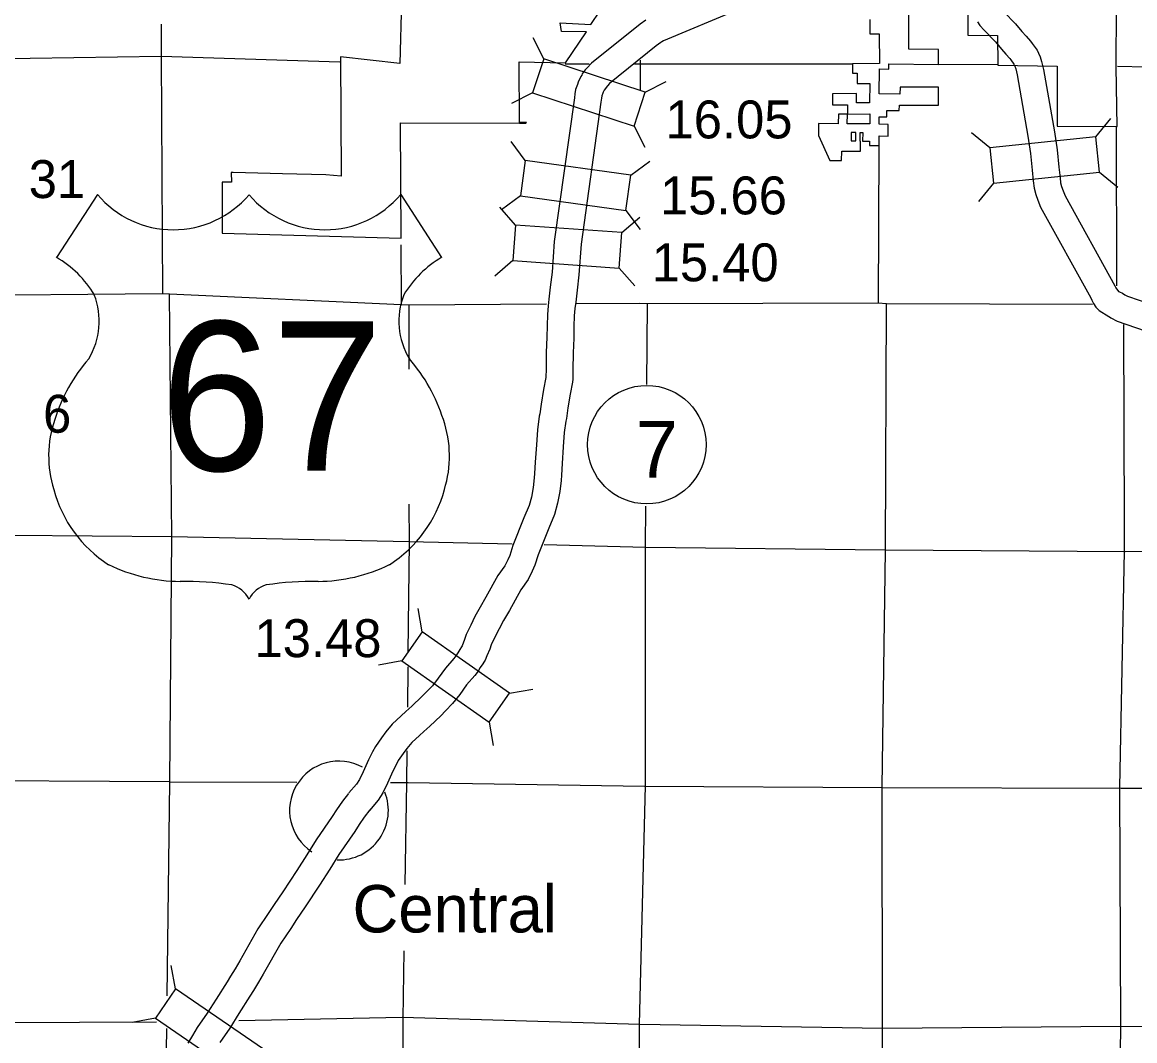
# Model space of a CAD drawing. Extents: x 369523 to 838377, y 495025 to 936819.
# Drawn here: x 641756 to 666534, y 838052 to 860745 of the extents above; entities that cross this region are included whole.
import ezdxf

# ---------------------------------------------------------------- set-up
doc = ezdxf.new("R2010")
doc.units = 0
for name, color, linetype in [('1', 7, 'Continuous'), ('6', 7, 'Continuous'), ('DSN_DRFT_Common-Line', 7, 'Continuous'), ('DSN_DRFT_Junk-No-Plot', 7, 'Continuous'), ('Level 1', 7, 'Continuous'), ('Level 11', 7, 'Continuous'), ('Level 15', 7, 'Continuous'), ('Level 2', 7, 'Continuous'), ('Level 21', 7, 'Continuous'), ('Level 22', 7, 'Continuous')]:
    doc.layers.add(name, color=color, linetype=linetype)

msp = doc.modelspace()

# ---------------------------------------------------------------- linework, layer by layer
at = {"layer": '1'}
for start, end in [(61.3406, 236.6749), (268.0667, 21.9061)]:
    msp.add_arc((648810, 843182), 1100, start, end, dxfattribs=at)
at = {"layer": '6'}
for p, q in [((643430, 856908), (642521, 855503)), ((650186, 856908), (651095, 855503))]:
    msp.add_line(p, q, dxfattribs=at)
for centre, radius, start, end in [((645122, 858332), 2211, 220.075, 319.6701), ((648494, 858332), 2211, 220.3299, 319.925), ((641334, 853463), 2361, 30.7809, 59.9883), ((652282, 853463), 2361, 120.0117, 149.2191), ((641853, 854085), 1618, 328.8105, 21.2108), ((651762, 854085), 1618, 158.7892, 211.1895), ((646085, 850768), 3776, 138.9565, 162.6913), ((647530, 850768), 3776, 17.3087, 41.0435), ((644839, 851077), 2495, 160.9576, 197.3819), ((648777, 851077), 2495, 342.6181, 19.0424), ((645245, 851084), 2887, 195.1074, 237.1312), ((648371, 851084), 2887, 302.8688, 344.8926), ((645299, 851994), 3707, 244.0771, 269.5779), ((648317, 851994), 3707, 270.4221, 295.9229), ((645384, 841498), 6790, 81.1942, 90.9539), ((646234, 847586), 651, 28.0342, 72.9864), ((647382, 847586), 651, 107.0136, 151.9658), ((648231, 841498), 6790, 89.0461, 98.8058)]:
    msp.add_arc(centre, radius, start, end, dxfattribs=at)
at = {"layer": 'DSN_DRFT_Common-Line'}
msp.add_circle((655666, 851334), 1320, dxfattribs=at)
at = {"layer": 'Level 1'}
for points in [[(663621, 860979), (663876, 860708), (664022, 860538), (664115, 860433), (664212, 860322), (664253, 860270), (664360, 860123), (664394, 860054), (664425, 859972), (664460, 859873), (664500, 859694), (664744, 858305), (664807, 857899), (664846, 857513), (664870, 857278), (664884, 857165), (664905, 857089), (664940, 856989), (664981, 856881), (666089, 854873), (666112, 854824), (666112, 854824), (666174, 854749), (666180, 854745), (666193, 854738), (666260, 854712), (666313, 854673), (666375, 854642), (667673, 854193)], [(663029, 860755), (663086, 860672), (663184, 860568), (663430, 860306), (663569, 860144), (663664, 860036), (663751, 859938), (663775, 859907), (663844, 859813), (663862, 859765), (663882, 859708), (663912, 859576), (664152, 858208), (664211, 857823), (664249, 857453), (664274, 857212), (664293, 857049), (664332, 856909), (664377, 856782), (664436, 856628), (665554, 854603), (665577, 854552), (665616, 854481), (665669, 854395), (665742, 854319), (665956, 854186), (665969, 854181), (666001, 854158), (666144, 854087), (667393, 853655)]]:
    msp.add_lwpolyline(points, dxfattribs=at)
at = {"layer": 'Level 11'}
for points in [[(655644, 860791), (655518, 860705), (654438, 859830), (654339, 859732), (654296, 859684), (654229, 859593), (654216, 859565), (654194, 859534), (654139, 859412), (654120, 859360), (654081, 859243), (654067, 859147), (654053, 859060), (653604, 855862), (653556, 855177), (653516, 854845), (653487, 854578), (653467, 854426), (653453, 854235), (653445, 853982), (653438, 853727), (653424, 853390), (653422, 853005), (653420, 852846), (653417, 852829), (653368, 852561), (653312, 852239), (653285, 852021), (653272, 851965), (653230, 851664), (653207, 851328), (653182, 850947), (653168, 850693), (653161, 850592), (653137, 850380), (653096, 850165), (653044, 849975), (652927, 849701), (652686, 849083), (652613, 848867), (652568, 848768), (652503, 848632), (652351, 848417), (652085, 847939), (651952, 847714), (651840, 847505), (651748, 847314), (651647, 847100), (651608, 846992), (651551, 846853), (651542, 846831), (651505, 846768), (651456, 846696), (651412, 846628), (651367, 846566), (651181, 846352), (651023, 846128), (650891, 845963), (650750, 845817), (650657, 845719), (650432, 845508), (650297, 845391), (650192, 845294), (649997, 845108), (649851, 844935), (649755, 844804), (649621, 844611), (649555, 844491), (649469, 844312), (649350, 844044), (649266, 843871), (649199, 843767), (649033, 843573)], [(657706, 861028), (656040, 860328), (656001, 860308), (655978, 860293), (655876, 860223), (654839, 859382), (654788, 859332), (654716, 859231), (654694, 859184), (654686, 859163), (654668, 859106), (654660, 859054), (654646, 858968), (654201, 855799), (654153, 855120), (654112, 854778), (654083, 854507), (654064, 854365), (654052, 854204), (654045, 853964), (654038, 853705), (654024, 853376), (654022, 853000), (654019, 852790), (654008, 852723), (653958, 852456), (653906, 852151), (653877, 851919), (653863, 851859), (653827, 851602), (653806, 851288), (653781, 850911), (653767, 850655), (653759, 850536), (653731, 850289), (653681, 850030), (653612, 849778), (653483, 849474), (653250, 848878), (653172, 848647), (653112, 848515), (653023, 848328), (652860, 848097), (652606, 847640), (652475, 847419), (652375, 847233), (652289, 847056), (652202, 846870), (652168, 846777), (652106, 846625), (652068, 846531), (652038, 846490), (652013, 846447), (651957, 846365), (651907, 846287), (651835, 846190), (651653, 845981), (651503, 845767), (651342, 845567), (651184, 845403), (651081, 845293), (650834, 845063), (650697, 844943), (650602, 844856), (650435, 844696), (650323, 844563), (650243, 844455), (650132, 844295), (650089, 844217), (650013, 844060), (649894, 843791), (649789, 843576), (649681, 843409), (649490, 843184)], [(649025, 843562), (648891, 843390), (648757, 843199), (648662, 843045), (648303, 842530), (648098, 842192), (647873, 841846), (647560, 841367), (647370, 841090), (647237, 840888), (647003, 840546), (646601, 839836), (646497, 839658), (646398, 839491), (646319, 839368), (646073, 838976), (645876, 838668), (645653, 838344), (645545, 838170), (645442, 837998)], [(649499, 843195), (649375, 843034), (649259, 842869), (649164, 842715), (648806, 842203), (648607, 841873), (648376, 841518), (648059, 841033), (647867, 840754), (647735, 840554), (647513, 840228), (647121, 839537), (647015, 839355), (646908, 839174), (646824, 839045), (646580, 838656), (646376, 838336), (646155, 838015)]]:
    msp.add_lwpolyline(points, dxfattribs=at)
at = {"layer": 'Level 15'}
for points in [[(644880, 854695), (639890, 854651), (634667, 854574), (634000, 854555)], [(653432, 854465), (650369, 854443), (650199, 854450), (645038, 854690), (644880, 854695)], [(665595, 854455), (661005, 854473), (660819, 854487), (655679, 854471), (655513, 854480), (654084, 854470)]]:
    msp.add_lwpolyline(points, dxfattribs=at)
at = {"layer": 'Level 2'}
for points in [[(660844, 860489), (660848, 859825), (660248, 859821), (660247, 859612), (660351, 859613), (660350, 859384), (660633, 859379), (660625, 858951), (660340, 858946), (660334, 859155), (659805, 859151), (659801, 858904), (660137, 858908), (660133, 858699), (660633, 858704), (660633, 858478), (660131, 858482), (660133, 858699), (659933, 858697), (659931, 858484), (659492, 858488), (659490, 858219), (659743, 857662), (660006, 857662), (660007, 857871), (660425, 857872), (660426, 858097), (660421, 858097), (660421, 858097), (660422, 858286), (660475, 858286), (660474, 858097), (660630, 858098), (660630, 858001), (660839, 858002), (660840, 858211), (661040, 858209), (661041, 858469), (660841, 858471), (660842, 858640), (661012, 858640), (661013, 858780), (661286, 858777), (661291, 858899), (662160, 858895), (662162, 859300), (661308, 859298), (661302, 859143), (660845, 859148), (660848, 859705), (661058, 859702), (661058, 859822), (662164, 859806), (662162, 860138), (661504, 860148), (661493, 861801)], [(650204, 861224), (650167, 859823), (648845, 859975), (648860, 857318), (648517, 857344), (647555, 857365), (646455, 857395), (646413, 857394), (646414, 857185), (646206, 857180), (646212, 856045), (650199, 855933), (650178, 858503), (652830, 858497)], [(662816, 861122), (662820, 860459), (663480, 860450), (663484, 859787), (664804, 859769), (664804, 858433), (666141, 858420), (666118, 859750), (666128, 861070)], [(652830, 858497), (652971, 858496), (652986, 858514), (652830, 858515), (652826, 859860), (653859, 859842), (654323, 860530), (653767, 860539), (653737, 860733), (654417, 860692), (654617, 860994)], [(660631, 860803), (660634, 860488), (660844, 860489)]]:
    msp.add_lwpolyline(points, dxfattribs=at)
msp.add_lwpolyline([(660321, 858103), (660321, 858285), (660220, 858285), (660219, 858103)], close=True, dxfattribs=at)
at = {"layer": 'Level 21'}
for p, q in [((653371, 859927), (653133, 860398)), ((655629, 859186), (656100, 859424)), ((653124, 859174), (652653, 858936)), ((665670, 858191), (666003, 858600)), ((655382, 858433), (655620, 857962)), ((652960, 857665), (652643, 858087)), ((663306, 857949), (662896, 858282)), ((655313, 857335), (655735, 857653)), ((665750, 857403), (666160, 857070)), ((663386, 857161), (663053, 856752)), ((652850, 856881), (652428, 856563)), ((652739, 856224), (652393, 856622)), ((655109, 856057), (655508, 856403)), ((655203, 856551), (655521, 856129)), ((652683, 855434), (652285, 855087)), ((655054, 855267), (655400, 854869)), ((650664, 847161), (650574, 847682)), ((650209, 846514), (649688, 846423)), ((652608, 845795), (653128, 845886)), ((652152, 845147), (652243, 844627)), ((645171, 839209), (645075, 839729)), ((644722, 838557), (644202, 838461))]:
    msp.add_line(p, q, dxfattribs=at)
for points in [[(655629, 859186), (653371, 859927), (653124, 859174), (655382, 858433)], [(663386, 857161), (665750, 857403), (665670, 858191), (663306, 857949)], [(655313, 857335), (652960, 857665), (652850, 856881), (655203, 856551)], [(652683, 855434), (655054, 855267), (655109, 856057), (652739, 856224)], [(650209, 846514), (652152, 845147), (652608, 845795), (650664, 847161)], [(647127, 837861), (645171, 839209), (644722, 838557), (646678, 837209)]]:
    msp.add_lwpolyline(points, close=True, dxfattribs=at)
at = {"layer": 'Level 22'}
for points in [[(644849, 860704), (644853, 859984), (644880, 854695)], [(644853, 859984), (639980, 859907), (639591, 859920)], [(648833, 859856), (644853, 859984)], [(654380, 859812), (653847, 859812)], [(660239, 859811), (655503, 859811), (655391, 859811)], [(655518, 859900), (655518, 859818), (655518, 859234)], [(663493, 859797), (662164, 859806)], [(660839, 859701), (660839, 859691)], [(667443, 859731), (666147, 859756)], [(666118, 858424), (666127, 854872)], [(660833, 858000), (660819, 854487)], [(660833, 858030), (660833, 858000)], [(650189, 855782), (650199, 854450)], [(644987, 839051), (645043, 843819), (645090, 849283), (645038, 854690)], [(650369, 854443), (650370, 853017)], [(655513, 854482), (655513, 854480)], [(655664, 852672), (655679, 854471)], [(660871, 822575), (660864, 827807), (660879, 833042), (660917, 838328), (660908, 843706), (660985, 848972), (661005, 854473)], [(666287, 854010), (666296, 849519)], [(650370, 850011), (650371, 849162), (650346, 846702)], [(655591, 822521), (655470, 827790), (655538, 833070), (655507, 838425), (655639, 843735), (655635, 849054), (655642, 849961)], [(666296, 849519), (666298, 848958), (666195, 843705), (666217, 838378), (666149, 833099), (666117, 827869), (666102, 822550)], [(645090, 849283), (639760, 849324)], [(652666, 849115), (650369, 849170), (645090, 849283)], [(670577, 848963), (666318, 848942), (660973, 848982), (655635, 849044), (653383, 849098)], [(650343, 846382), (650334, 845482)], [(650325, 844509), (650318, 843804), (650280, 841533)], [(645043, 843819), (639655, 843854)], [(645043, 843819), (647872, 843813)], [(649955, 843809), (650348, 843808), (655618, 843721), (660910, 843698), (666231, 843677), (671344, 843677)], [(650256, 840056), (650231, 838543), (650217, 833139), (650120, 827864), (650155, 822450)], [(671402, 838361), (666219, 838368), (660914, 838322), (655508, 838411), (650218, 838571), (646579, 838498)], [(644743, 838465), (639585, 838445)], [(644962, 837351), (644977, 838324)]]:
    msp.add_lwpolyline(points, dxfattribs=at)

# ---------------------------------------------------------------- texts
at = {"layer": '1'}
msp.add_text('Central', height=1056, dxfattribs=at).set_placement((649113, 840465))
at = {"layer": '6'}
msp.add_text('67', height=3326.4, dxfattribs=at).set_placement((644841, 850754))
at = {"layer": 'DSN_DRFT_Common-Line'}
msp.add_text('7', height=1267, dxfattribs=at).set_placement((655418, 850595))
at = {"layer": 'DSN_DRFT_Junk-No-Plot'}
for s, p in [('16.05', (656084, 858157)), ('15.66', (655961, 856464)), ('15.40', (655775, 854973)), ('13.48', (646930, 846599))]:
    msp.add_text(s, height=844.8, dxfattribs=at).set_placement(p)
at = {"layer": 'Level 22'}
for s, height, p in [('31', 844.8, (641900, 856828)), ('6', 845, (642220, 851599))]:
    msp.add_text(s, height=height, dxfattribs=at).set_placement(p)

doc.saveas('drawing.dxf')
